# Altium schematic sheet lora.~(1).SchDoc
size A4
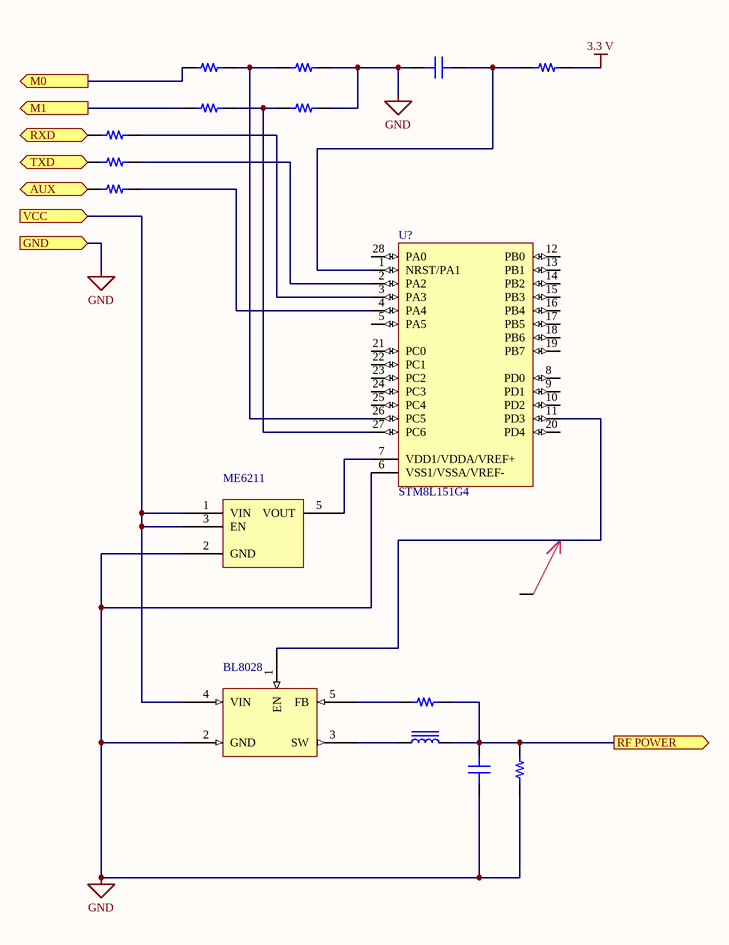
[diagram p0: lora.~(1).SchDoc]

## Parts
(Parts that share a designator on the sheet are numbered #1, #2 ... from top to bottom, then left to right.)
?#1  10 kOhms  [RES 0402_1005]  (value not drawn)
?#2  10 kOhms  [RES 0402_1005]  (value not drawn)
?#3  150pF  [CAP 0402_1005]  (value not drawn)
?#4  10 kOhms  [RES 0402_1005]  (value not drawn)
?#5  10 kOhms  [RES 0402_1005]  (value not drawn)
?#6  10 kOhms  [RES 0402_1005]  (value not drawn)
?#7  10 kOhms  [RES 0402_1005]  (value not drawn)
?#8  10 kOhms  [RES 0402_1005]  (value not drawn)
?#9  10 kOhms  [RES 0402_1005]  (value not drawn)
?#10  10 kOhms  [RES 0402_1005]  (value not drawn)
?#11  BL8028  [BL8028 SOT-23-5 W5]
?#12  1.5µH  [BOURNS SRP5030T]  (value not drawn)
?#13  150pF  [CAP 0402_1005]  (value not drawn)
?#14  10 kOhms  [RES 0402_1005]  (value not drawn)
ME6211  TPS76327DBVR  [TI SOT-23-5 DBV]  (value not drawn)
U?  STM8L151G4  [UFQFPN28_V]

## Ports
AUX (out), GND (in), M0 (out), M1 (out), RF POWER (out), RXD (in), TXD (out), VCC (in)

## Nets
3.3 V: ?#4.2
GND: ?#2.2 ?#3.1 ?#6.2 ?#11.2(GND) ?#13.1 ?#14.1 ME6211.2(GND) U?.6(VSS1/VSSA/VREF-) ; port GND
AUX: ?#9.1 ; port AUX
M0: ?#1.1 ; port M0
M1: ?#5.1 ; port M1
RF POWER: ?#10.2 ?#12.2 ?#13.2 ?#14.2 ; port RF POWER
RXD: ?#7.1 ; port RXD
TXD: ?#8.1 ; port TXD
VCC: ?#11.4(VIN) ME6211.1(VIN) ME6211.3(EN) ; port VCC
Net?#1_2: ?#1.2 ?#2.1 U?.26(PC5)
Net?#3_2: ?#3.2 ?#4.1 U?.1(NRST/PA1)
Net?#5_2: ?#5.2 ?#6.1 U?.27(PC6)
Net?#7_2: ?#7.2 U?.3(PA3)
Net?#8_2: ?#8.2 U?.2(PA2)
Net?#9_2: ?#9.2 U?.4(PA4)
Net?#10_1: ?#10.1 ?#11.5(FB)
Net?#11_1: ?#11.1(EN) U?.11(PD3)
Net?#11_3: ?#11.3(SW) ?#12.1
NetME6211_5: ME6211.5(VOUT) U?.7(VDD1/VDDA/VREF+)

Not connected (* = marked no-connect by the designer): U? 5(PA5) 8(PD0) 9(PD1) 10(PD2) 12(PB0) 13(PB1) 14(PB2) 15(PB3) 16(PB4) 17(PB5) 18(PB6) 19(PB7) 20(PD4) 21(PC0) 22(PC1) 23(PC2) 24(PC3) 25(PC4) 28(PA0)

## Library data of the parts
?#1 ?#2 ?#4-?#10 ?#14 = AC0402JR-0710KL: RES SMD 10K OHM 5% 1/16W 0402; Manufacturer: Yageo; Power (Watts): 0.063W, 1/16W; Temperature Coefficient: ±100ppm/°C
?#3 ?#13 = C0402C151F5GAC7867: CAP CER 150PF 50V NP0 0402; Manufacturer: KEMET; Temperature Coefficient: C0G, NP0; Tolerance: ±1%
?#11 = SHANGHAI BELLING SOT23-5 out 5V: Step- down switching regulators 6v in max; Part Number: GUxx; Manufacturer: Diodes Incorporated; Control Features: Enable; Current - Output: 600mA; Current - Quiescent (Iq): 80µA; Number of Regulators: 1; Output Configuration: Positive; Output Type: Fixed; Protection Features: Over Current, Over Temperature; PSRR: 65sB (100Hz ~ 1KHz); Voltage Dropout (Max): 0.7V @ 600mA; Voltage - Output (Min/Fixed): 5 v
?#12 = SRP5030T-1R5M: FIXED IND 1.5UH 6A 25 MOHM SMD; Manufacturer: Bourns Inc.; Current - Saturation: 10A; DC Resistance (DCR): 25mOhm Max; Inductance Frequency - Test: 100kHz; Material - Core: Iron Powder; Shielding: Shielded; Tolerance: ±20%
ME6211 = TPS76327DBVR: IC REG LINEAR 2.7V 150MA SOT23-5; Manufacturer: Texas Instruments; Control Features: Enable; Current - Quiescent (Iq): 100µA; Current - Supply (Max): 140µA; Number of Regulators: 1; Output Configuration: Positive; Output Type: Fixed; Protection Features: Over Current, Over Temperature, Reverse Polarity; PSRR: 60dB (1kHz); Voltage - Input (Max): 10V
U? = STM8L151G4: STM8L ARM-based EnergyLite 8-bit MCU, 16 kB Flash, 2 kB Internal RAM, 28-pin UFQFPN, Tape and Reel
